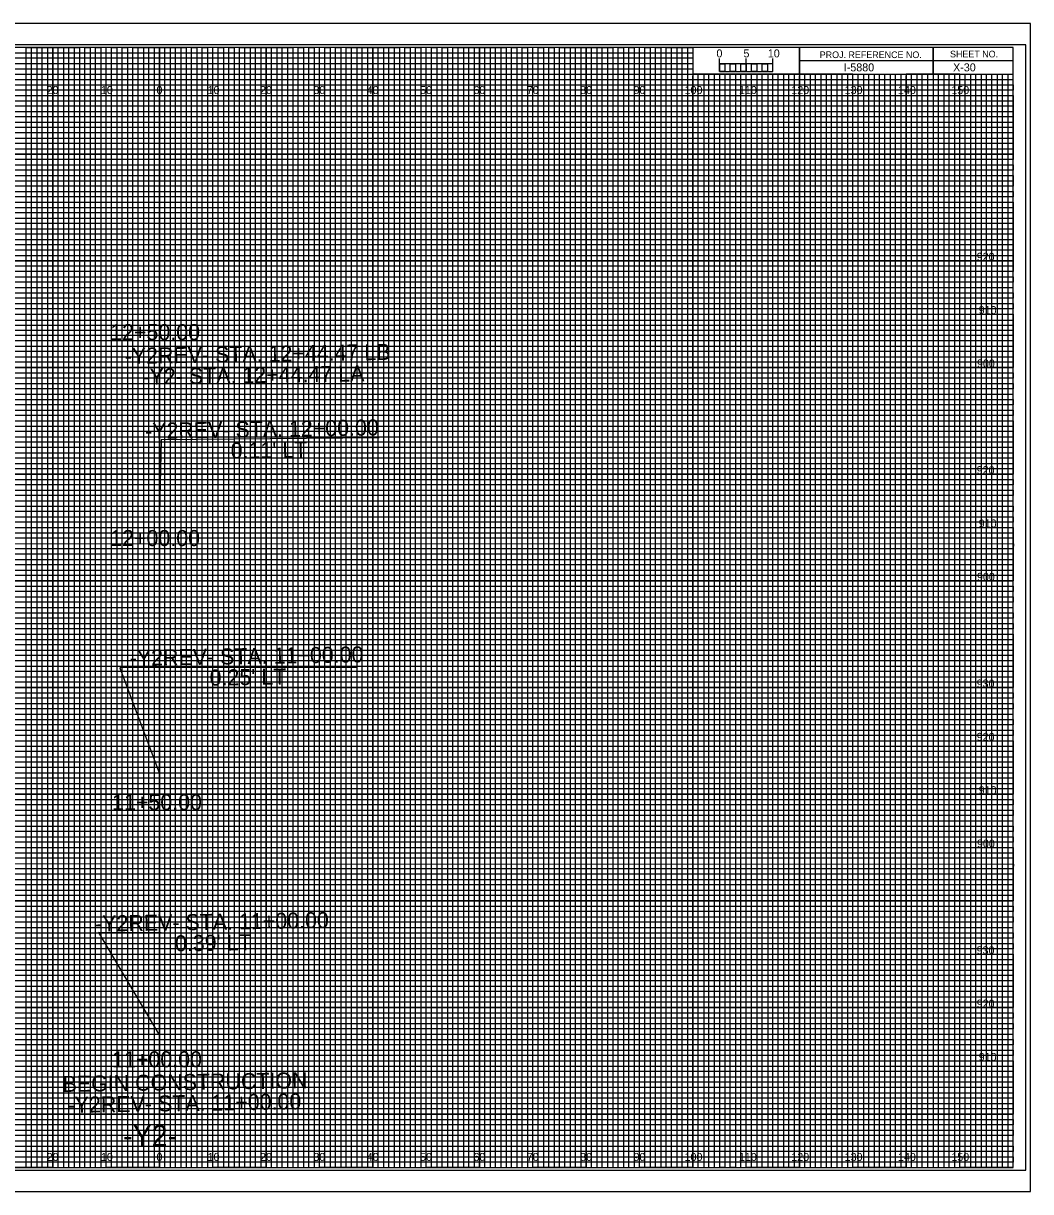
# Model space of a CAD drawing. Extents: x -13 to 323, y -4 to 214.
# Drawn here: x 134.5 to 323.3, y -4.5 to 214.5 of the extents above; entities that cross this region are included whole.
import ezdxf

# ---------------------------------------------------------------- set-up
doc = ezdxf.new("R2010")
doc.units = 0
for name, color, linetype in [('Prop XS Alignment Label', 7, 'Continuous'), ('Prop XS Bar Scale Labels', 7, 'Continuous'), ('Prop XS Elevation Labels', 7, 'Continuous'), ('Prop XS Offset Labels', 7, 'Continuous'), ('Prop XS Project Number', 7, 'Continuous'), ('Prop XS SE Text', 7, 'Continuous'), ('Prop XS Sheet Number', 7, 'Continuous'), ('Prop XS Station Labels', 7, 'Continuous'), ('Sheet Cross Section CELL', 7, 'Continuous'), ('Sheet Cross Section Grid Major CELL', 7, 'Continuous'), ('Sheet Cross Section Grid Middle CELL', 7, 'Continuous'), ('Sheet Cross Section Grid Minor 1 CELL', 7, 'Continuous'), ('Sheet Cross Section Grid Minor 2 CELL', 7, 'Continuous'), ('Sheet Cross Section Scale CELL', 7, 'Continuous'), ('Sheet Cutting Line CELL', 7, 'Continuous'), ('Sheet DOT Grid CELL', 7, 'Continuous'), ('Sheet Plot Border Inside CELL', 7, 'Continuous'), ('Sheet Plot Border Outside CELL', 7, 'Continuous')]:
    doc.layers.add(name, color=color, linetype=linetype)

msp = doc.modelspace()

# ---------------------------------------------------------------- linework, layer by layer
at = {"layer": 'Prop XS SE Text'}
for p, q in [((160.31, 136.43), (160.01, 122.68)), ((201.22, 136.83), (160.31, 136.43)), ((197.04, 93.77), (152.57, 93.68)), ((152.57, 93.68), (159.96, 74.03)), ((183.91, 43.91), (148.58, 44.06)), ((148.58, 44.06), (160, 24.79))]:
    msp.add_line(p, q, dxfattribs=at)
at = {"layer": 'Sheet Cross Section CELL'}
for p, q in [((305, 210), (305, 205)), ((305, 205), (305, 210)), ((280, 207.5), (280, 205)), ((320, 207.49), (280, 207.49)), ((280, 205), (320, 205))]:
    msp.add_line(p, q, dxfattribs=at)
for points in [[(320, 210), (0, 210), (0, 0), (320, 0)], [(280, 210), (260, 210), (260, 205.03), (280, 205.03)], [(320, 210), (280, 210), (280, 205), (320, 205)]]:
    msp.add_lwpolyline(points, close=True, dxfattribs=at)
at = {"layer": 'Sheet Cross Section Grid Major CELL'}
for p, q in [((150, 210), (140, 210)), ((140, 210), (140, 0)), ((150, 0), (150, 210)), ((170, 210), (160, 210)), ((160, 210), (160, 0)), ((170, 0), (170, 210)), ((190, 210), (180, 210)), ((180, 210), (180, 0)), ((190, 0), (190, 210)), ((210, 210), (200, 210)), ((200, 210), (200, 0)), ((210, 0), (210, 210)), ((230, 210), (220, 210)), ((220, 210), (220, 0)), ((230, 0), (230, 210)), ((250, 210), (240, 210)), ((240, 210), (240, 0)), ((250, 0), (250, 210)), ((260, 210), (260, 0)), ((270, 0), (270, 205)), ((290, 205), (280, 205)), ((280, 205), (280, 0)), ((290, 0), (290, 205)), ((310, 205), (300, 205)), ((300, 205), (300, 0)), ((310, 0), (310, 205)), ((140, 0), (130, 0)), ((160, 0), (150, 0)), ((180, 0), (170, 0)), ((200, 0), (190, 0)), ((220, 0), (210, 0)), ((240, 0), (230, 0)), ((260, 0), (250, 0)), ((280, 0), (270, 0)), ((300, 0), (290, 0)), ((320, 0), (310, 0)), ((320, 0), (320, 0))]:
    msp.add_line(p, q, dxfattribs=at)
for points in [[(0, 200), (320, 200), (320, 190), (0, 190)], [(0, 180), (320, 180), (320, 170), (0, 170)], [(0, 160), (320, 160), (320, 150), (0, 150)], [(0, 140), (320, 140), (320, 130), (0, 130)], [(0, 120), (320, 120), (320, 110), (0, 110)], [(0, 100), (320, 100), (320, 90), (0, 90)], [(0, 80), (320, 80), (320, 70), (0, 70)], [(0, 60), (320, 60), (320, 50), (0, 50)], [(0, 40), (320, 40), (320, 30), (0, 30)], [(0, 20), (320, 20), (320, 10), (0, 10)]]:
    msp.add_lwpolyline(points, dxfattribs=at)
at = {"layer": 'Sheet Cross Section Grid Middle CELL'}
for points in [[(125, 0), (135, 0), (135, 210), (145, 210), (145, 0), (155, 0), (155, 210), (165, 210), (165, 0), (175, 0), (175, 210), (185, 210), (185, 0), (195, 0), (195, 210), (205, 210), (205, 0), (215, 0), (215, 210), (225, 210), (225, 0), (235, 0), (235, 210), (245, 210), (245, 0), (255, 0), (255, 210), (259.93, 210), (260, 210), (260, 205), (264.99, 205), (264.99, 0), (275, 0), (275, 205), (285, 205), (285, 0), (295, 0), (295, 205), (305, 205), (305, 0), (315, 0), (315, 205)], [(0, 205), (275, 205)], [(0, 185), (320, 185), (320, 195), (0, 195)], [(0, 165), (320, 165), (320, 175), (0, 175)], [(0, 145), (320, 145), (320, 155), (0, 155)], [(0, 125), (320, 125), (320, 135), (0, 135)], [(0, 105), (320, 105), (320, 115), (0, 115)], [(0, 85), (320, 85), (320, 95), (0, 95)], [(0, 65), (320, 65), (320, 75), (0, 75)], [(0, 45), (320, 45), (320, 55), (0, 55)], [(0, 25), (320, 25), (320, 35), (0, 35)], [(0, 5), (320, 5), (320, 15), (0, 15)]]:
    msp.add_lwpolyline(points, dxfattribs=at)
at = {"layer": 'Sheet Cross Section Grid Minor 1 CELL'}
for p, q in [((0, 209), (260, 209)), ((260, 209), (260, 207.98)), ((260, 207.98), (0, 207.98)), ((0, 207), (260, 207)), ((260, 205.89), (0, 205.89)), ((260, 207), (260, 205.89)), ((0, 204), (320, 204))]:
    msp.add_line(p, q, dxfattribs=at)
for points in [[(0, 203), (270, 203), (320, 203), (320, 202), (0, 202)], [(0, 201), (320, 201), (320, 199), (0, 199)], [(0, 198), (320, 198), (320, 197), (0, 196.98)], [(0, 196), (320, 196), (320, 194), (0, 194)], [(0, 193), (320, 193), (320, 192), (0, 192)], [(0, 191), (320, 191), (320, 189), (0, 189)], [(0, 188), (320, 188), (320, 187), (0, 187)], [(0, 186), (320, 186), (320, 184), (0, 184)], [(0, 183), (320, 183), (320, 182), (0, 182)], [(0, 181), (320, 181), (320, 179), (0, 179)], [(0, 178), (320, 178), (320, 177), (0, 177)], [(0, 176), (320, 176), (320, 173.95), (320, 173), (320, 172), (0, 172)], [(0, 174), (320, 174), (320, 173), (0, 173)], [(0, 171), (320, 171), (320, 169), (0, 169.03)], [(0, 169.03), (320, 169), (320, 168), (0, 168)], [(0, 167), (320, 167), (320, 166), (0, 166)], [(0, 164), (320, 164), (320, 163), (0, 163)], [(0, 162), (320, 162), (320, 161), (0, 161)], [(-0.07, 158.89), (320, 158.89), (320, 157.88), (-0.07, 157.88)], [(0, 157), (320, 157), (320, 156), (0, 156)], [(0, 154), (320, 154), (320, 153), (0, 153)], [(0, 152), (320, 152), (320, 151), (0, 151)], [(0, 149), (320, 149), (320, 148), (0, 148)], [(0, 147), (320, 147), (320, 146), (0, 146)], [(0, 144), (320, 144), (320, 143), (0, 143)], [(0, 142), (320, 142), (320, 141), (0, 141)], [(0, 139), (320, 139), (319.99, 137.98), (0, 138)], [(0, 137), (320, 137), (320, 136), (0, 136)], [(0, 134), (320, 134), (320, 133), (0, 133)], [(0, 132), (320, 132), (320, 131), (0, 131)], [(0, 129), (320, 129), (320, 128), (0, 128)], [(0, 127), (320, 127), (320, 126), (0, 126)], [(0, 124), (320, 124), (320, 123), (0, 123)], [(0, 122), (320, 122), (320, 121), (0, 121)], [(0, 119), (320, 119), (320, 118), (0, 118)], [(0, 116.99), (320.07, 116.91), (320, 116), (0, 116)], [(0, 114), (320, 114), (320, 113), (0, 113)], [(0, 112), (320, 112), (320, 111), (0, 111)], [(0, 109), (320, 109), (320, 108), (0, 108)], [(0, 107), (320, 107), (320, 106), (0, 106)], [(0, 104), (320, 104), (320, 103), (0, 103)], [(0, 102), (320, 102), (320, 101), (0, 101)], [(0, 99), (320, 99), (320, 98), (0, 98)], [(0, 97), (320, 97), (320, 96), (0, 96)], [(0, 94), (320, 94), (320, 93), (0, 93)], [(0, 92), (320, 92), (320, 91), (0, 91)], [(0, 89), (320, 89), (320, 88), (0, 88)], [(0, 87), (320, 87), (320, 86), (0, 86)], [(0, 84), (320, 84), (320, 83), (0, 83)], [(0, 82), (320, 82), (320, 81), (0, 81)], [(0, 79), (320, 79), (319.99, 77.98), (0, 78)], [(0, 77), (320, 77), (320, 76), (0, 76)], [(0, 74), (320, 74), (320, 73), (0, 73)], [(0, 72), (320, 72), (320, 71), (0, 71)], [(0, 69), (320, 69), (320, 68), (0, 68)], [(0, 67), (320, 67), (320, 66), (0, 66)], [(0, 64), (320, 64), (320, 63), (0, 63)], [(0, 62), (320, 62), (320, 61), (0, 61)], [(0, 59), (320, 59), (320, 58), (0, 58)], [(0, 56.99), (320.07, 56.91), (320, 56), (0, 56)], [(0, 54), (320, 54), (320, 53), (0, 53)], [(0, 52), (320, 52), (320, 51), (0, 51)], [(0, 49), (320, 49), (320, 48), (0, 48)], [(0, 47), (320, 47), (320, 46), (0, 46)], [(0, 44), (320, 44), (320, 43), (0, 43)], [(0, 42), (320, 42), (320, 41), (0, 41)], [(0, 39), (320, 39), (320, 38), (0, 38)], [(0, 37), (320, 37), (320, 36), (0, 36)], [(0, 34), (320, 34), (320, 33), (0, 33)], [(0, 32), (320, 32), (320, 31), (0, 31)], [(0, 29), (320, 29), (320, 28), (0, 28)], [(0, 27), (320, 27), (320, 26), (0, 26)], [(0, 24), (320, 24), (320, 23), (0, 23)], [(0, 22), (320, 22), (320, 21), (0, 21)], [(0, 19), (320, 19), (320, 18), (0, 18)], [(0, 17), (320, 17), (320, 16), (0, 16)], [(0, 14), (320, 14), (320, 13), (0, 13)], [(0, 12), (320, 12), (320, 11), (0, 11)], [(0, 9), (320, 9), (320, 8), (0, 8)], [(0, 7), (320, 7), (320, 6), (0, 6)], [(0, 4), (320, 4), (320, 3), (0, 3)], [(0, 2), (320, 2), (320, 1), (0, 1)]]:
    msp.add_lwpolyline(points, dxfattribs=at)
at = {"layer": 'Sheet Cross Section Grid Minor 2 CELL'}
for p, q in [((267, 205), (266.01, 205)), ((266.01, 205), (266.01, 0)), ((267, 0), (267, 205)), ((269, 205), (268, 205)), ((268, 205), (268, 0)), ((269, 0), (269, 205)), ((266.01, 0), (265, 0)), ((268, 0), (267, 0))]:
    msp.add_line(p, q, dxfattribs=at)
for points in [[(135, 0), (136, 0), (136, 210), (137, 210), (137, 0)], [(137, 0), (138, 0), (138, 210), (139, 210), (139, 0)], [(140, 0), (141, 0), (141, 210), (142, 210), (142, 0)], [(142, 0), (143, 0), (143, 210), (144, 210), (144, 0)], [(145, 0), (146, 0), (146, 210), (147, 210), (147, 0)], [(147, 0), (148, 0), (148, 210), (149, 210), (149, 0)], [(150, 0), (151, 0), (151, 210), (152, 210), (152, 0)], [(152, 0), (153, 0), (153, 210), (154, 210), (154, 0)], [(155, 0), (156, 0), (156, 210), (157, 210), (157, 0)], [(157, 0), (158, 0), (158, 210), (159, 210), (159, 0)], [(160, 0), (161, 0), (161, 210), (162, 210), (162, 0)], [(162, 0), (163, 0), (163, 210), (164, 210), (164, 0)], [(165, 0), (166, 0), (166, 210), (167, 210), (167, 0)], [(167, 0), (168, 0), (168, 210), (169, 210), (169, 0)], [(170, 0), (171, 0), (171, 210), (172, 210), (172, 0)], [(172, 0), (173, 0), (173, 210), (174, 210), (174, 0)], [(175, 0), (176, 0), (176, 210), (177, 210), (177, 0)], [(177, 0), (178, 0), (178, 210), (179, 210), (179, 0)], [(180, 0), (181, 0), (181, 210), (182, 210), (182, 0)], [(182, 0), (183, 0), (183, 210), (184, 210), (184, 0)], [(185, 0), (186, 0), (186, 210), (187, 210), (187, 0)], [(187, 0), (188, 0), (188, 210), (189, 210), (189, 0)], [(190, 0), (191, 0), (191, 210), (192, 210), (192, 0)], [(192, 0), (193, 0), (193, 210), (194, 210), (194, 0)], [(195, 0), (196, 0), (196, 210), (197, 210), (197, 0)], [(197, 0), (198, 0), (198, 210), (199, 210), (199, 0)], [(200, 0), (201, 0), (201, 210), (202, 210), (202, 0)], [(202, 0), (203, 0), (203, 210), (204, 210), (204, 0)], [(205, 0), (206, 0), (206, 210), (207, 210), (207, 0)], [(207, 0), (208, 0), (208, 210), (209, 210), (209, 0)], [(210, 0), (211, 0), (211, 210), (212, 210), (212, 0)], [(212, 0), (213, 0), (213, 210), (214, 210), (214, 0)], [(215, 0), (216, 0), (216, 210), (217, 210), (217, 0)], [(217, 0), (218, 0), (218, 210), (219, 210), (219, 0)], [(220, 0), (221, 0), (221, 210), (222, 210), (222, 0)], [(222, 0), (223, 0), (223, 210), (224, 210), (224, 0)], [(225, 0), (226, 0), (226, 210), (227, 210), (227, 0)], [(227, 0), (228, 0), (228, 210), (229, 210), (229, 0)], [(230, 0), (231, 0), (231, 210), (232, 210), (232, 0)], [(232, 0), (233, 0), (233, 210), (234, 210), (234, 0)], [(235, 0), (236, 0), (236, 210), (237, 210), (237, 0)], [(237, 0), (238, 0), (238, 210), (239, 210), (239, 0)], [(240, 0), (241, 0), (241, 210), (242, 210), (242, 0)], [(242, 0), (243, 0), (243, 210), (244, 210), (244, 0)], [(245, 0), (246, 0), (246, 210), (247, 210), (247, 0)], [(247, 0), (248, 0), (248, 210), (249, 210), (249, 0)], [(250, 0), (251, 0), (251, 210), (252, 210), (252, 0)], [(252, 0), (253, 0), (253, 210), (254, 210), (254, 0)], [(255, 0), (256, 0), (256, 210), (257, 210), (257, 0)], [(257, 0), (258, 0), (258, 210), (259, 210), (259, 0)], [(260, 0), (261, 0), (261, 205), (262.02, 205), (262.02, 0)], [(262, 0), (263, 0), (263, 205), (263.99, 205), (263.99, 0)], [(270, 0), (270.98, 0), (270.98, 205), (272, 205), (272, 0)], [(272, 0), (273, 0), (273, 205), (274.05, 205), (274.05, 0)], [(275, 0), (276, 0), (276, 205), (277, 205), (277, 0)], [(277, 0), (278, 0), (278, 205), (279, 205), (279, 0)], [(280, 0), (281, 0), (281, 205), (282, 205), (282, 0)], [(282, 0), (283, 0), (283, 205), (284, 205), (284, 0)], [(285, 0), (286, 0), (286, 205), (287, 205), (287, 0)], [(287, 0), (288, 0), (288, 205), (289, 205), (289, 0)], [(290, 0), (291, 0), (291, 205), (292, 205), (292, 0)], [(292, 0), (293, 0), (293, 205), (294, 205), (294, 0)], [(295, 0), (296, 0), (296, 205), (297, 205), (297, 0)], [(297, 0), (298, 0), (298, 205), (299, 205), (299, 0)], [(300, 0), (301, 0), (301, 205), (302, 205), (302, 0)], [(302, 0), (303, 0), (303, 205), (304, 205), (304, 0)], [(305, 0), (306, 0), (306, 205), (307, 205), (307, 0)], [(307, 0), (308, 0), (308, 205), (309, 205), (309, 0)], [(310, 0), (311, 0), (311, 205), (312, 205), (312, 0)], [(312, 0), (313, 0), (313, 205), (314, 205), (314, 0)], [(315, 0), (316, 0), (316, 205), (317, 205), (317, 0)], [(317, 0), (318, 0), (318, 205), (319, 205), (319, 0)]]:
    msp.add_lwpolyline(points, dxfattribs=at)
at = {"layer": 'Sheet Cross Section Scale CELL'}
for p, q in [((265, 205.49), (265, 207.9)), ((265, 206.9), (265, 207.9)), ((270, 205.49), (270, 207.9)), ((275, 205.49), (275, 207.9)), ((275, 206.9), (275, 207.9))]:
    msp.add_line(p, q, dxfattribs=at)
for points in [[(275, 206.9), (265, 206.9), (265, 205.49), (275, 205.49)], [(265, 206.9), (266, 206.9), (266, 205.49), (265, 205.49)], [(267, 206.9), (268, 206.9), (268, 205.49), (267, 205.49)], [(269, 206.9), (270, 206.9), (270, 205.49), (269, 205.49)], [(271, 206.9), (272, 206.9), (272, 205.49), (271, 205.49)], [(273, 206.9), (274, 206.9), (274, 205.49), (273, 205.49)]]:
    msp.add_lwpolyline(points, close=True, dxfattribs=at)
at = {"layer": 'Sheet Cutting Line CELL'}
for p, q in [((323.3, 214.5), (-13.4, 214.5)), ((-13.4, -4.5), (323.3, -4.5))]:
    msp.add_line(p, q, dxfattribs=at)
at = {"layer": 'Sheet DOT Grid CELL'}
for p, q in [((140, 0), (140, 210)), ((150, 0), (150, 210)), ((160, 0), (160, 210)), ((170, 0), (170, 210)), ((180, 0), (180, 210)), ((190, 0), (190, 210)), ((200, 0), (200, 210)), ((210, 0), (210, 210)), ((220, 0), (220, 210)), ((230, 0), (230, 210)), ((240, 0), (240, 210)), ((250, 0), (250, 210)), ((260, 0), (260, 204.69)), ((270, 0), (270, 204.69)), ((280, 0), (280, 204.69)), ((290, 0), (290, 204.69)), ((300, 0), (300, 204.69)), ((310, 0), (310, 204.69)), ((0, 200), (320, 200)), ((0, 190), (320, 190)), ((0, 180), (320, 180)), ((0, 170), (320, 170)), ((0, 160), (320, 160)), ((0, 150), (320, 150)), ((0, 140), (320, 140)), ((0, 130), (320, 130)), ((0, 120), (320, 120)), ((0, 110), (320, 110)), ((0, 100), (320, 100)), ((0, 90), (320, 90)), ((0, 80), (320, 80)), ((0, 70), (320, 70)), ((0, 60), (320, 60)), ((0, 50), (320, 50)), ((0, 40), (320, 40)), ((0, 30), (320, 30)), ((0, 20), (320, 20)), ((0, 10), (320, 10))]:
    msp.add_line(p, q, dxfattribs=at)
at = {"layer": 'Sheet Plot Border Inside CELL'}
msp.add_lwpolyline([(-10.8, -0.5), (322.4, -0.5), (322.4, 210.5), (-10.8, 210.5)], close=True, dxfattribs=at)
at = {"layer": 'Sheet Plot Border Outside CELL'}
msp.add_lwpolyline([(-13.4, -4.5), (323.3, -4.5), (323.3, 214.5), (-13.4, 214.5)], close=True, dxfattribs=at)

# ---------------------------------------------------------------- texts
at = {"layer": 'Prop XS Alignment Label'}
msp.add_text('-Y2-', height=4, dxfattribs=at).set_placement((153.21, 4))
at = {"layer": 'Prop XS Bar Scale Labels'}
for s, p in [('5', (269.47, 208.12)), ('10', (274.04, 208.12))]:
    msp.add_text(s, height=1.5, dxfattribs=at).set_placement(p)
at = {"layer": 'Prop XS Elevation Labels'}
for s, p in [('920', (313.19, 170)), ('910', (313.57, 160)), ('900', (313.24, 150)), ('920', (313.19, 130)), ('910', (313.57, 120)), ('900', (313.24, 110)), ('930', (313.18, 90)), ('920', (313.19, 80)), ('910', (313.57, 70)), ('900', (313.24, 60)), ('930', (313.18, 40)), ('920', (313.19, 30)), ('910', (313.57, 20))]:
    msp.add_text(s, height=1.5, dxfattribs=at).set_placement(p)
at = {"layer": 'Prop XS Offset Labels'}
for s, p in [('20', (138.86, 201.25)), ('10', (149.04, 201.25)), ('0', (159.45, 201.25)), ('0', (159.45, 201.25)), ('10', (169.04, 201.25)), ('20', (178.86, 201.25)), ('30', (188.86, 201.25)), ('40', (198.86, 201.25)), ('50', (208.86, 201.25)), ('60', (218.86, 201.25)), ('70', (228.86, 201.25)), ('80', (238.86, 201.25)), ('90', (248.86, 201.25)), ('100', (258.44, 201.25)), ('110', (268.62, 201.25)), ('120', (278.44, 201.25)), ('130', (288.44, 201.25)), ('140', (298.44, 201.25)), ('150', (308.44, 201.25)), ('20', (138.86, 1.25)), ('10', (149.04, 1.25)), ('0', (159.45, 1.25)), ('0', (159.45, 1.25)), ('10', (169.04, 1.25)), ('20', (178.86, 1.25)), ('30', (188.86, 1.25)), ('40', (198.86, 1.25)), ('50', (208.86, 1.25)), ('60', (218.86, 1.25)), ('70', (228.86, 1.25)), ('80', (238.86, 1.25)), ('90', (248.86, 1.25)), ('100', (258.44, 1.25)), ('110', (268.62, 1.25)), ('120', (278.44, 1.25)), ('130', (288.44, 1.25)), ('140', (298.44, 1.25)), ('150', (308.44, 1.25))]:
    msp.add_text(s, height=1.5, dxfattribs=at).set_placement(p)
at = {"layer": 'Prop XS Project Number'}
msp.add_text('I-5880', height=1.5, dxfattribs=at).set_placement((288.28, 205.5))
at = {"layer": 'Prop XS SE Text'}
for s, p in [('-Y2REV- STA. 12+44.47 LB', (153.51, 150.65)), ('-Y2- STA. 12+44.47 LA', (156.85, 146.76)), ('-Y2REV- STA. 12+00.00', (157.33, 136.59)), ("0.11' LT", (173.38, 132.91)), ('-Y2REV- STA. 11+00.00', (154.45, 94.05)), ("0.25' LT", (169.43, 90.35)), ('-Y2REV- STA. 11+00.00', (147.96, 44.24)), ("0.39' LT", (162.94, 40.54)), ('BEGIN CONSTRUCTION', (141.87, 14.18)), ('-Y2REV- STA. 11+00.00', (142.8, 10.26))]:
    msp.add_text(s, height=3, rotation=0.887, dxfattribs=at).set_placement(p)
at = {"layer": 'Prop XS Sheet Number'}
msp.add_text('X-30', height=1.5, dxfattribs=at).set_placement((308.77, 205.5))
at = {"layer": 'Prop XS Station Labels'}
for s, p in [('12+50.00', (150.77, 155.12)), ('12+00.00', (150.77, 116.52)), ('11+50.00', (151.13, 67.01)), ('11+00.00', (151.13, 18.81))]:
    msp.add_text(s, height=3, dxfattribs=at).set_placement(p)
at = {"layer": 'Sheet Cross Section CELL'}
for s, p in [('PROJ. REFERENCE NO.', (283.77, 207.99)), ('SHEET NO.', (308.19, 208.12))]:
    msp.add_text(s, height=1.25, dxfattribs=at).set_placement(p)
at = {"layer": 'Sheet Cross Section Scale CELL'}
msp.add_text('0', height=1.5, dxfattribs=at).set_placement((264.41, 208.12))

doc.saveas('drawing.dxf')
